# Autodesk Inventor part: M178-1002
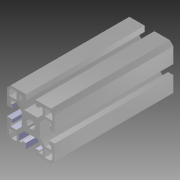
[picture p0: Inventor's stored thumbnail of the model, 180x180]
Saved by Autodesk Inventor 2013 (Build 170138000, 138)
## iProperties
Created: 2004-10
Material: Aluminium - 6061
Document SubType Name: Modeling
Designer: Autodesk, Inc.
Manufacturer: Standard
Standards Organization: Custom
Description: TABLE, SUPPORT BAR, FRONT/BACK
Stock Number: 10-040
Catalog Web Link: http://www.parker.com/ead/cm1.asp?cmid=809
Vendor: PARKER IPS
Part Number: M178-1002
Mass: 179.948 g
Surface Area: 483.565 cm^2
Volume: 66.4013 cm^3
Density: 2.71 g/cm^3
CAGE: 1LJX3
Dept. ID: Product Design
Description #2: ---
Finish #1: ---
Finish #2: ---
Material ID: ---
Project Number: ---
Length: 1828.800 mm
Author: Autodesk, Inc.
Revision Number: A
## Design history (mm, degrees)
derived "40 Series Profiles.ipt"
body "Solid1"
tag "TaggingFeature2"
feature "Solid1::40 Series Profiles.ipt" dims "ScaleForDerivedMember" = 10
other parameters: "Length" = 1828.8
